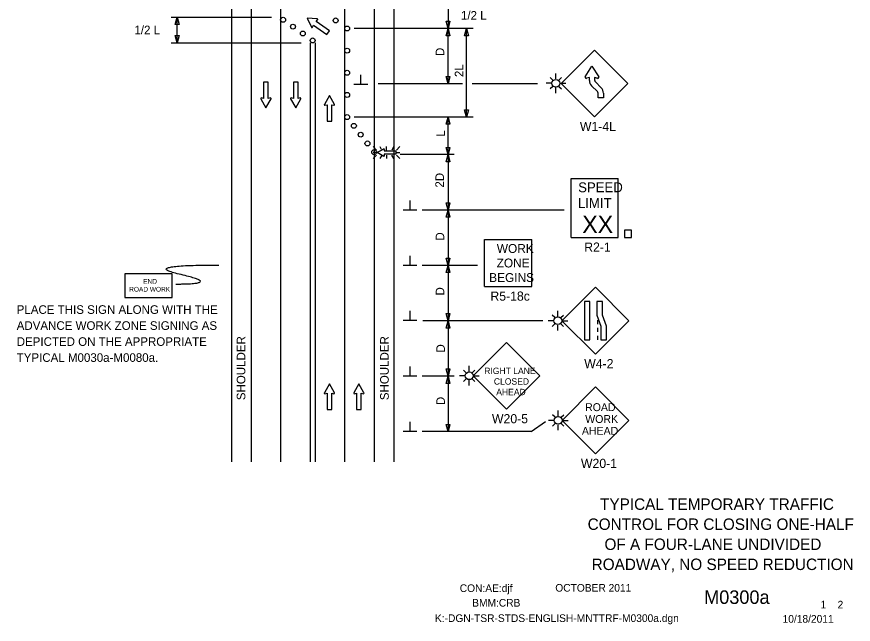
# Model space of a CAD drawing. Extents: x 16731 to 18475, y 7218 to 8213.
# Drawn here: x 16731 to 17410, y 7218 to 7712 of the extents above; entities that cross this region are included whole.
import ezdxf

# ---------------------------------------------------------------- set-up
doc = ezdxf.new("R2010")
doc.units = 0
for name, color, linetype in [('ALI_LEGAL_EX', 7, 'Continuous'), ('BORDER_SIGNAL_WO', 7, 'Continuous'), ('MT_SCRATCH_LEVEL_E', 7, 'Continuous'), ('PAVT_EDGE_EX', 7, 'Continuous'), ('TRAFFIC_SIGNS_PR', 7, 'Continuous'), ('TYPICAL_TEXT_DIMEN_PR', 7, 'Continuous')]:
    doc.layers.add(name, color=color, linetype=linetype)

msp = doc.modelspace()

# ---------------------------------------------------------------- linework, layer by layer
at = {"layer": 'ALI_LEGAL_EX'}
for p, q in [((16945.19, 8201.12), (16945.19, 7350.01)), ((16997.19, 8201.12), (16997.19, 7350.01))]:
    msp.add_line(p, q, dxfattribs=at)
for points in [[(16945.19, 7701.12), (16945.19, 7676.12)], [(16997.19, 7701.12), (16997.19, 7676.12)], [(16945.19, 7601.12), (16945.19, 7576.12)], [(16997.19, 7590.68), (16997.19, 7576.12)], [(16945.19, 7501.12), (16945.19, 7476.12)], [(16997.19, 7501.12), (16997.19, 7476.12)], [(16945.19, 7401.12), (16945.19, 7376.12)], [(16997.19, 7401.12), (16997.19, 7376.12)]]:
    msp.add_lwpolyline(points, dxfattribs=at)
at = {"layer": 'MT_SCRATCH_LEVEL_E'}
for p, q in [((16966.63, 7710.63), (16970.21, 7703.11)), ((16974.94, 7709.88), (16966.63, 7710.63)), ((16966.63, 7710.63), (16970.21, 7703.11)), ((16974.94, 7709.88), (16966.63, 7710.63)), ((16973.95, 7707.82), (16975.23, 7709.1)), ((16973.95, 7707.82), (16975.23, 7709.1)), ((16984.82, 7700.23), (16973.95, 7707.82)), ((16984.82, 7700.23), (16973.95, 7707.82)), ((16971.05, 7703.11), (16971.81, 7704.75)), ((16971.05, 7703.11), (16971.81, 7704.75)), ((16971.81, 7704.75), (16982.68, 7697.16)), ((16971.81, 7704.75), (16982.68, 7697.16)), ((16982.68, 7697.16), (16984.82, 7700.23)), ((16982.68, 7697.16), (16984.82, 7700.23)), ((16935.11, 7658.61), (16931.37, 7658.61)), ((16931.37, 7658.61), (16931.37, 7645.35)), ((16935.11, 7658.61), (16931.37, 7658.61)), ((16931.37, 7658.61), (16931.37, 7645.35)), ((16935.11, 7645.35), (16935.11, 7658.61)), ((16935.11, 7645.35), (16935.11, 7658.61)), ((16959.29, 7658.61), (16955.55, 7658.61)), ((16955.55, 7658.61), (16955.55, 7645.35)), ((16959.29, 7658.61), (16955.55, 7658.61)), ((16955.55, 7658.61), (16955.55, 7645.35)), ((16959.29, 7645.35), (16959.29, 7658.61)), ((16959.29, 7645.35), (16959.29, 7658.61)), ((16929.11, 7644.98), (16933.26, 7637.74)), ((16929.11, 7644.98), (16933.26, 7637.74)), ((16931.37, 7645.35), (16929.59, 7645.66)), ((16931.37, 7645.35), (16929.59, 7645.66)), ((16933.26, 7637.74), (16937.37, 7644.98)), ((16933.26, 7637.74), (16937.37, 7644.98)), ((16936.89, 7645.66), (16935.11, 7645.35)), ((16936.89, 7645.66), (16935.11, 7645.35)), ((16953.29, 7644.98), (16957.44, 7637.74)), ((16953.29, 7644.98), (16957.44, 7637.74)), ((16955.55, 7645.35), (16953.77, 7645.66)), ((16955.55, 7645.35), (16953.77, 7645.66)), ((16957.44, 7637.74), (16961.55, 7644.98)), ((16957.44, 7637.74), (16961.55, 7644.98)), ((16961.07, 7645.66), (16959.29, 7645.35)), ((16961.07, 7645.66), (16959.29, 7645.35)), ((16984.79, 7647.72), (16980.68, 7640.48)), ((16984.79, 7647.72), (16980.68, 7640.48)), ((16988.93, 7640.48), (16984.79, 7647.72)), ((16988.93, 7640.48), (16984.79, 7647.72)), ((16981.16, 7639.79), (16982.94, 7640.11)), ((16981.16, 7639.79), (16982.94, 7640.11)), ((16982.94, 7640.11), (16982.94, 7626.85)), ((16982.94, 7640.11), (16982.94, 7626.85)), ((16986.68, 7626.85), (16986.68, 7640.11)), ((16986.68, 7640.11), (16988.45, 7639.79)), ((16986.68, 7626.85), (16986.68, 7640.11)), ((16986.68, 7640.11), (16988.45, 7639.79)), ((16982.94, 7626.85), (16986.68, 7626.85)), ((16982.94, 7626.85), (16986.68, 7626.85)), ((16984.79, 7413.36), (16980.68, 7406.12)), ((16984.79, 7413.36), (16980.68, 7406.12)), ((16988.93, 7406.12), (16984.79, 7413.36)), ((16988.93, 7406.12), (16984.79, 7413.36)), ((17008.71, 7413.36), (17004.6, 7406.12)), ((17008.71, 7413.36), (17004.6, 7406.12)), ((17012.86, 7406.12), (17008.71, 7413.36)), ((17012.86, 7406.12), (17008.71, 7413.36)), ((16981.16, 7405.43), (16982.94, 7405.75)), ((16981.16, 7405.43), (16982.94, 7405.75)), ((16982.94, 7405.75), (16982.94, 7392.49)), ((16982.94, 7405.75), (16982.94, 7392.49)), ((16986.68, 7392.49), (16986.68, 7405.75)), ((16986.68, 7405.75), (16988.45, 7405.43)), ((16986.68, 7392.49), (16986.68, 7405.75)), ((16986.68, 7405.75), (16988.45, 7405.43)), ((17005.08, 7405.43), (17006.86, 7405.75)), ((17005.08, 7405.43), (17006.86, 7405.75)), ((17006.86, 7405.75), (17006.86, 7392.49)), ((17006.86, 7405.75), (17006.86, 7392.49)), ((17010.6, 7392.49), (17010.6, 7405.75)), ((17010.6, 7405.75), (17012.38, 7405.43)), ((17010.6, 7392.49), (17010.6, 7405.75)), ((17010.6, 7405.75), (17012.38, 7405.43)), ((16982.94, 7392.49), (16986.68, 7392.49)), ((16982.94, 7392.49), (16986.68, 7392.49)), ((17006.86, 7392.49), (17010.6, 7392.49)), ((17006.86, 7392.49), (17010.6, 7392.49))]:
    msp.add_line(p, q, dxfattribs=at)
for centre, start, end in [((16974.89, 7709.42), 315.10498, 84.84191), ((16974.89, 7709.42), 315.10498, 84.84191), ((16970.63, 7703.32), 205.49363, 335.0326), ((16970.63, 7703.32), 205.49363, 335.0326), ((16929.52, 7645.2), 80.03619, 209.77312), ((16929.52, 7645.2), 80.03619, 209.77312), ((16936.96, 7645.21), 330.42484, 99.96381), ((16936.96, 7645.21), 330.42484, 99.96381), ((16953.7, 7645.2), 80.03619, 209.77312), ((16953.7, 7645.2), 80.03619, 209.77312), ((16961.14, 7645.21), 330.42484, 99.96381), ((16961.14, 7645.21), 330.42484, 99.96381), ((16981.08, 7640.25), 150.42484, 279.96381), ((16981.08, 7640.25), 150.42484, 279.96381), ((16988.52, 7640.25), 260.03619, 29.77312), ((16988.52, 7640.25), 260.03619, 29.77312), ((16981.08, 7405.89), 150.42484, 279.96381), ((16981.08, 7405.89), 150.42484, 279.96381), ((16988.52, 7405.89), 260.03619, 29.77312), ((16988.52, 7405.89), 260.03619, 29.77312), ((17005.01, 7405.89), 150.42484, 279.96381), ((17005.01, 7405.89), 150.42484, 279.96381), ((17012.45, 7405.89), 260.03619, 29.77312), ((17012.45, 7405.89), 260.03619, 29.77312)]:
    msp.add_arc(centre, 0.463, start, end, dxfattribs=at)
at = {"layer": 'PAVT_EDGE_EX'}
for p, q in [((16905.19, 8201.12), (16905.19, 7350.01)), ((16921.19, 8201.12), (16921.19, 7350.01)), ((17021.19, 8201.12), (17021.19, 7350.01)), ((17037.19, 8201.12), (17037.19, 7350.01)), ((16969.19, 7690.45), (16969.19, 7350.01)), ((16973.19, 7690.45), (16973.19, 7350.01))]:
    msp.add_line(p, q, dxfattribs=at)
at = {"layer": 'TRAFFIC_SIGNS_PR'}
for p, q in [((17172.93, 7657.41), (17200.08, 7684.57)), ((17227.23, 7657.41), (17200.08, 7684.57)), ((17168.75, 7661.17), (17168.75, 7665.67)), ((17166.24, 7660.13), (17164.13, 7662.24)), ((17171.27, 7660.13), (17173.38, 7662.24)), ((17200.83, 7658.66), (17205.55, 7653.95)), ((17205.55, 7653.95), (17200.84, 7658.66)), ((17165.6, 7657.62), (17160.76, 7657.62)), ((17166.24, 7655.11), (17164.13, 7653)), ((17168.75, 7649.65), (17168.75, 7654.06)), ((17171.27, 7655.11), (17173.37, 7653)), ((17171.91, 7657.62), (17176.79, 7657.62)), ((17200.08, 7630.26), (17172.93, 7657.41)), ((17202.5, 7650.89), (17197.78, 7655.61)), ((17202.5, 7650.89), (17197.78, 7655.61)), ((17227.23, 7657.41), (17200.08, 7630.26)), ((17020.32, 7606.12), (17023.14, 7603.3)), ((17025.76, 7606.12), (17026.97, 7604.03)), ((17031.23, 7603.3), (17031.23, 7606.12)), ((17037.02, 7606.12), (17035.39, 7603.3)), ((17039.31, 7603.3), (17042.13, 7606.12)), ((17023.14, 7601.27), (17020.32, 7601.27)), ((17020.32, 7596.42), (17023.14, 7599.24)), ((17027.05, 7598.6), (17025.78, 7596.42)), ((17031.23, 7599.24), (17031.23, 7596.42)), ((17035.36, 7599.24), (17036.99, 7596.42)), ((17039.31, 7601.27), (17042.13, 7601.27)), ((17039.31, 7599.24), (17042.13, 7596.42)), ((17181.1, 7580.24), (17219.5, 7580.24)), ((17181.1, 7532.24), (17181.1, 7580.24)), ((17219.5, 7532.24), (17219.5, 7580.24)), ((17110.77, 7492.43), (17110.77, 7530.83)), ((17110.77, 7530.83), (17149.17, 7530.83)), ((17149.17, 7492.43), (17149.17, 7530.83)), ((17181.1, 7532.24), (17219.5, 7532.24)), ((17110.77, 7492.43), (17149.17, 7492.43)), ((17200.83, 7491.87), (17173.68, 7464.72)), ((17227.98, 7464.72), (17200.83, 7491.87)), ((17167.85, 7467.23), (17165.74, 7469.34)), ((17170.36, 7468.27), (17170.36, 7472.77)), ((17172.87, 7467.23), (17174.98, 7469.34)), ((17167.21, 7464.72), (17162.37, 7464.72)), ((17167.85, 7462.2), (17165.74, 7460.09)), ((17172.87, 7462.2), (17174.98, 7460.1)), ((17173.51, 7464.72), (17178.39, 7464.72)), ((17173.68, 7464.72), (17200.83, 7437.57)), ((17200.83, 7437.57), (17227.98, 7464.72)), ((17202.47, 7465.21), (17202.47, 7462.01)), ((17170.36, 7456.75), (17170.36, 7461.16)), ((17202.47, 7458.81), (17202.47, 7455.61)), ((17202.47, 7452.41), (17202.47, 7449.21)), ((17128.66, 7447.14), (17101.51, 7419.98)), ((17155.82, 7419.98), (17128.66, 7447.14)), ((17098.36, 7423.54), (17098.36, 7428.04)), ((17095.84, 7422.5), (17093.74, 7424.61)), ((17100.87, 7422.5), (17102.98, 7424.61)), ((17095.2, 7419.98), (17090.37, 7419.98)), ((17095.84, 7417.47), (17093.74, 7415.36)), ((17098.36, 7412.02), (17098.36, 7416.43)), ((17100.87, 7417.47), (17102.98, 7415.36)), ((17101.51, 7419.98), (17106.39, 7419.98)), ((17101.51, 7419.98), (17128.66, 7392.83)), ((17128.66, 7392.83), (17155.82, 7419.98)), ((17200.97, 7410.91), (17173.78, 7383.73)), ((17228.16, 7383.73), (17200.97, 7410.91)), ((17168.12, 7386.24), (17166.01, 7388.35)), ((17170.63, 7387.28), (17170.63, 7391.78)), ((17173.14, 7386.24), (17175.25, 7388.35)), ((17167.47, 7383.73), (17162.64, 7383.73)), ((17168.11, 7381.21), (17166.01, 7379.1)), ((17170.63, 7375.76), (17170.63, 7380.17)), ((17173.14, 7381.21), (17175.25, 7379.11)), ((17173.78, 7383.73), (17200.97, 7356.54)), ((17173.78, 7383.73), (17178.66, 7383.73)), ((17200.97, 7356.54), (17228.16, 7383.73))]:
    msp.add_line(p, q, dxfattribs=at)
for points in [[(17192.63, 7662.94), (17198.11, 7671.55), (17203.59, 7662.94)], [(17192.63, 7662.94), (17198.11, 7671.55), (17203.59, 7662.94)], [(17195.96, 7659.92), (17195.95, 7662.29), (17193.59, 7661.64)], [(17195.96, 7659.92), (17195.95, 7662.29), (17193.59, 7661.64)], [(17202.63, 7661.64), (17200.27, 7662.29), (17200.27, 7659.99)], [(17202.63, 7661.64), (17201.8, 7661.87), (17200.27, 7662.29), (17200.27, 7659.99)], [(17207.42, 7649.53), (17207.42, 7645.83), (17203.1, 7645.83), (17203.1, 7649.53)], [(17028.9, 7598.26), (17023.59, 7601.27), (17028.9, 7604.31)], [(17029.4, 7603.95), (17029.17, 7602.66), (17038.89, 7602.66), (17038.89, 7599.91), (17029.17, 7599.91), (17029.4, 7598.61)]]:
    msp.add_lwpolyline(points, dxfattribs=at)
for points in [[(17224.52, 7532.24), (17230.11, 7532.24), (17230.11, 7538.41), (17224.52, 7538.41)], [(16818.57, 7483.63), (16856.97, 7483.63), (16856.97, 7502.83), (16818.57, 7502.83)], [(17191.93, 7480.46), (17191.93, 7449.21), (17196.43, 7449.21), (17196.43, 7480.46)], [(17202.07, 7480.46), (17202.07, 7469.27), (17205.41, 7460.39), (17205.41, 7449.21), (17209.91, 7449.21), (17209.91, 7460.39), (17206.56, 7469.27), (17206.56, 7480.46)]]:
    msp.add_lwpolyline(points, close=True, dxfattribs=at)
for centre, radius in [((16947.19, 7709.21), 2), ((16947.19, 7709.21), 2), ((16947.19, 7709.21), 2), ((16989.88, 7708.68), 2), ((16955.19, 7703.62), 2), ((16963.19, 7698.04), 2), ((16999.22, 7702.15), 2), ((16971.19, 7692.45), 2), ((16999.22, 7684.15), 2), ((16999.22, 7666.15), 2), ((17168.75, 7657.62), 3.15), ((16999.22, 7648.15), 2), ((16999.22, 7630.15), 2), ((17004.71, 7623.02), 2), ((17010.21, 7615.89), 2), ((17015.71, 7608.76), 2), ((17021.21, 7601.64), 2), ((17170.36, 7464.72), 3.15), ((17098.36, 7419.98), 3.15), ((17170.63, 7383.73), 3.15)]:
    msp.add_circle(centre, radius, dxfattribs=at)
for centre, radius, start, end in [((17193.36, 7662.47), 0.866, 147.7292, 285.31719), ((17193.36, 7662.47), 0.866, 147.71964, 285.32011), ((17183.52, 7668.73), 10.8, 327.53351, 327.54311), ((17196.44, 7651.22), 10.8, 105.31922, 105.32004), ((17202.13, 7659.99), 6.17, 180.61811, 225.78746), ((17202.13, 7659.99), 6.17, 180.62445, 225.23128), ((17202.13, 7659.99), 1.85, 179.8762, 225.7877), ((17202.13, 7659.99), 1.85, 180, 225.78746), ((17202.86, 7662.47), 0.866, 254.61481, 32.47119), ((17201.25, 7649.53), 6.17, 0, 45.78828), ((17201.25, 7649.53), 1.85, 0, 47.62801), ((17029.07, 7604.01), 0.341, 350.04067, 118.51671), ((17029.07, 7598.56), 0.341, 241.10835, 9.26922)]:
    msp.add_arc(centre, radius, start, end, dxfattribs=at)
msp.add_open_spline([(16860.12, 7494.51), (16897.91, 7494.51), (16829.89, 7509.98), (16895.07, 7509.98)], degree=2, dxfattribs=at)
at = {"layer": 'TYPICAL_TEXT_DIMEN_PR'}
for p, q in [((17081.19, 7723.73), (17081.19, 7702.15)), ((16856.19, 7711.21), (16937.73, 7711.21)), ((16859.62, 7705.35), (16861.19, 7711.21)), ((16861.19, 7690.45), (16861.19, 7711.21)), ((16861.19, 7711.21), (16862.76, 7705.35)), ((17081.19, 7702.15), (17079.62, 7708.02)), ((17079.62, 7708.02), (17081.19, 7708.02)), ((17081.19, 7708.02), (17082.76, 7708.02)), ((17082.76, 7708.02), (17081.19, 7702.15)), ((16861.19, 7705.35), (16859.62, 7705.35)), ((16862.76, 7705.35), (16861.19, 7705.35)), ((17101.62, 7702.15), (17004.96, 7702.15)), ((17079.62, 7696.29), (17081.19, 7702.15)), ((17081.19, 7657.15), (17081.19, 7702.15)), ((17081.19, 7702.15), (17082.76, 7696.29)), ((17094.62, 7696.29), (17096.19, 7702.15)), ((17096.19, 7630.15), (17096.19, 7702.15)), ((17096.19, 7702.15), (17097.76, 7696.29)), ((16861.19, 7690.45), (16859.62, 7696.31)), ((16859.62, 7696.31), (16861.19, 7696.31)), ((16861.19, 7696.31), (16862.76, 7696.31)), ((16862.76, 7696.31), (16861.19, 7690.45)), ((17081.19, 7696.29), (17079.62, 7696.29)), ((17082.76, 7696.29), (17081.19, 7696.29)), ((17096.19, 7696.29), (17094.62, 7696.29)), ((17097.76, 7696.29), (17096.19, 7696.29)), ((16856.19, 7690.45), (16961.73, 7690.45)), ((17010.35, 7656.61), (17010.35, 7664.4)), ((17081.19, 7657.15), (17079.62, 7663.02)), ((17079.62, 7663.02), (17081.19, 7663.02)), ((17081.19, 7663.02), (17082.76, 7663.02)), ((17082.76, 7663.02), (17081.19, 7657.15)), ((17015.98, 7656.61), (17004.73, 7656.61)), ((17092.83, 7657.15), (17024.38, 7657.15)), ((17153.84, 7657.15), (17100.74, 7657.15)), ((17096.19, 7630.15), (17094.62, 7636.01)), ((17094.62, 7636.01), (17096.19, 7636.01)), ((17096.19, 7636.01), (17097.76, 7636.01)), ((17097.76, 7636.01), (17096.19, 7630.15)), ((17101.62, 7630.15), (17004.96, 7630.15)), ((17079.62, 7624.29), (17081.19, 7630.15)), ((17081.19, 7599.64), (17081.19, 7630.15)), ((17081.19, 7630.15), (17082.76, 7624.29)), ((17081.19, 7624.29), (17079.62, 7624.29)), ((17082.76, 7624.29), (17081.19, 7624.29)), ((17081.19, 7599.64), (17079.62, 7605.5)), ((17079.62, 7605.5), (17081.19, 7605.5)), ((17081.19, 7605.5), (17082.76, 7605.5)), ((17082.76, 7605.5), (17081.19, 7599.64)), ((17086.19, 7599.64), (17042.21, 7599.64)), ((17079.62, 7593.78), (17081.19, 7599.64)), ((17081.19, 7599.64), (17081.19, 7554.64)), ((17081.19, 7599.64), (17082.76, 7593.78)), ((17081.19, 7593.78), (17079.62, 7593.78)), ((17082.76, 7593.78), (17081.19, 7593.78)), ((17050.32, 7554.64), (17050.32, 7562.43)), ((17081.19, 7554.64), (17079.62, 7560.5)), ((17079.62, 7560.5), (17081.19, 7560.5)), ((17081.19, 7560.5), (17082.76, 7560.5)), ((17082.76, 7560.5), (17081.19, 7554.64)), ((17055.94, 7554.64), (17044.69, 7554.64)), ((17175.59, 7554.64), (17060.19, 7554.64)), ((17079.62, 7548.78), (17081.19, 7554.64)), ((17081.19, 7554.64), (17082.76, 7548.78)), ((17081.19, 7554.64), (17081.19, 7509.64)), ((17081.19, 7548.78), (17079.62, 7548.78)), ((17082.76, 7548.78), (17081.19, 7548.78)), ((17050.32, 7509.64), (17050.32, 7517.43)), ((17055.94, 7509.64), (17044.69, 7509.64)), ((17105.15, 7509.64), (17060.19, 7509.64)), ((17081.19, 7509.64), (17079.62, 7515.5)), ((17079.62, 7515.5), (17081.19, 7515.5)), ((17079.62, 7503.78), (17081.19, 7509.64)), ((17081.19, 7515.5), (17082.76, 7515.5)), ((17082.76, 7515.5), (17081.19, 7509.64)), ((17081.19, 7509.71), (17081.19, 7464.71)), ((17081.19, 7509.64), (17082.76, 7503.78)), ((17081.19, 7503.78), (17079.62, 7503.78)), ((17082.76, 7503.78), (17081.19, 7503.78)), ((17050.32, 7464.91), (17050.32, 7472.69)), ((17081.19, 7464.64), (17079.62, 7470.5)), ((17079.62, 7470.5), (17081.19, 7470.5)), ((17081.19, 7470.5), (17082.76, 7470.5)), ((17082.76, 7470.5), (17081.19, 7464.64)), ((17055.94, 7464.91), (17044.69, 7464.91)), ((17158.19, 7464.64), (17060.81, 7464.64)), ((17079.62, 7458.78), (17081.19, 7464.64)), ((17081.19, 7464.64), (17081.19, 7419.64)), ((17081.19, 7464.64), (17082.76, 7458.78)), ((17081.19, 7458.78), (17079.62, 7458.78)), ((17082.76, 7458.78), (17081.19, 7458.78)), ((17050.32, 7419.64), (17050.32, 7427.43)), ((17081.19, 7419.64), (17079.62, 7425.5)), ((17079.62, 7425.5), (17081.19, 7425.5)), ((17081.19, 7425.5), (17082.76, 7425.5)), ((17082.76, 7425.5), (17081.19, 7419.64)), ((17055.94, 7419.64), (17044.69, 7419.64)), ((17086.19, 7419.64), (17060.19, 7419.64)), ((17079.62, 7413.78), (17081.19, 7419.64)), ((17081.19, 7419.64), (17082.76, 7413.78)), ((17081.19, 7419.64), (17081.19, 7374.64)), ((17081.19, 7413.78), (17079.62, 7413.78)), ((17082.76, 7413.78), (17081.19, 7413.78)), ((17050.32, 7374.64), (17050.32, 7382.43)), ((17081.19, 7374.64), (17079.62, 7380.5)), ((17079.62, 7380.5), (17081.19, 7380.5)), ((17081.19, 7380.5), (17082.76, 7380.5)), ((17082.76, 7380.5), (17081.19, 7374.64)), ((17148.68, 7374.64), (17160.26, 7382.7)), ((17055.94, 7374.64), (17044.69, 7374.64)), ((17148.68, 7374.64), (17060.19, 7374.64))]:
    msp.add_line(p, q, dxfattribs=at)

# ---------------------------------------------------------------- texts
at = {"layer": 'BORDER_SIGNAL_WO'}
for s, height, p in [('TYPICAL TEMPORARY TRAFFIC', 9.3, (17204.66, 7311.05)), ('CONTROL FOR CLOSING ONE-HALF', 9.3, (17194.57, 7294.75)), ('OF A FOUR-LANE UNDIVIDED', 9.3, (17208.25, 7278.45)), ('ROADWAY, NO SPEED REDUCTION', 9.3, (17197.83, 7262.15)), ('CON:AE:djf', 6.2, (17090.69, 7244.31)), ('    OCTOBER 2011    ', 6.2, (17159.08, 7244.59)), ('    M0300a   ', 11, (17272.86, 7234.63)), ('BMM:CRB   ', 6.2, (17100.81, 7232.42)), (' 1    2 ', 6.2, (17381.45, 7230.95)), (' 1    2 ', 6.2, (17381.45, 7230.95)), (' 1    2 ', 6.2, (17381.45, 7230.95)), ('K:-DGN-TSR-STDS-ENGLISH-MNTTRF-M0300a.dgn        ', 6.2, (17070.55, 7219.96)), ('10/18/2011    ', 6.2, (17352.93, 7219.38))]:
    msp.add_text(s, height=height, dxfattribs=at).set_placement(p)
at = {"layer": 'TRAFFIC_SIGNS_PR'}
for s, height, p in [('W1-4L', 7.44, (17188.28, 7618.82)), ('SPEED', 8, (17186.87, 7569.1)), ('LIMIT', 8, (17186.7, 7556.3)), ('XX', 14.031, (17190.21, 7535.99)), ('WORK', 7.217, (17120.77, 7519.8)), ('R2-1', 7.44, (17191.78, 7520.8)), ('ZONE', 7.217, (17120.65, 7507.99)), ('BEGINS', 7.217, (17114.58, 7496.18)), ('END', 3.831, (16833.57, 7494.76)), ('ROAD WORK', 3.831, (16822.18, 7488.38)), ('R5-18c', 7.44, (17115.58, 7480.99)), ('PLACE THIS SIGN ALONG WITH THE', 7, (16730.78, 7470.27)), ('ADVANCE WORK ZONE SIGNING AS', 7, (16730.78, 7457.27)), ('DEPICTED ON THE APPROPRIATE', 7, (16730.78, 7444.27)), ('TYPICAL M0030a-M0080a.', 7, (16730.78, 7431.27)), ('W4-2', 7.44, (17191.79, 7426.13)), ('RIGHT LANE', 5.2, (17110.58, 7421.38)), ('CLOSED', 5.2, (17118.38, 7412.78)), ('AHEAD', 5.2, (17120.32, 7404.18)), ('ROAD', 6.408, (17192.5, 7391.27)), ('W20-5', 7.44, (17116.84, 7381.39)), ('WORK', 6.408, (17192.61, 7381.66)), ('AHEAD', 6.408, (17189.91, 7372.05)), ('W20-1', 7.449, (17189.12, 7345.08))]:
    msp.add_text(s, height=height, dxfattribs=at).set_placement(p)
at = {"layer": 'TYPICAL_TEXT_DIMEN_PR'}
for p in [(17091.66, 7709.28), (16826.39, 7697.43)]:
    msp.add_text('1/2 L', height=7, dxfattribs=at).set_placement(p)
for s, p in [('D', (17078.1, 7679.76)), ('2L', (17093.63, 7662.65)), ('L', (17078.63, 7614.25)), ('2D', (17077.83, 7572.87)), ('D', (17078.1, 7529.8)), ('D', (17078.1, 7485.19)), ('SHOULDER', (16916.51, 7400.16)), ('SHOULDER', (17033.01, 7400.16)), ('D', (17078.63, 7438.86)), ('D', (17078.63, 7396.15))]:
    msp.add_text(s, height=7, rotation=90, dxfattribs=at).set_placement(p)

doc.saveas('drawing.dxf')
